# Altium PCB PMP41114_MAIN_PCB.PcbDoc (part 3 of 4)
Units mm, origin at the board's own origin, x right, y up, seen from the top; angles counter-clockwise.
Board outline 159.1 x 70 mm, 6 copper layers (Top Layer, Signal Layer 1, Signal Layer 2, Signal Layer 3, Signal Layer 4, Bottom Layer), stack 1.671 mm thick; 188 components, 146 nets, 720 pads, 326 vias.
Unrouted connection lines stored in the file: 209.
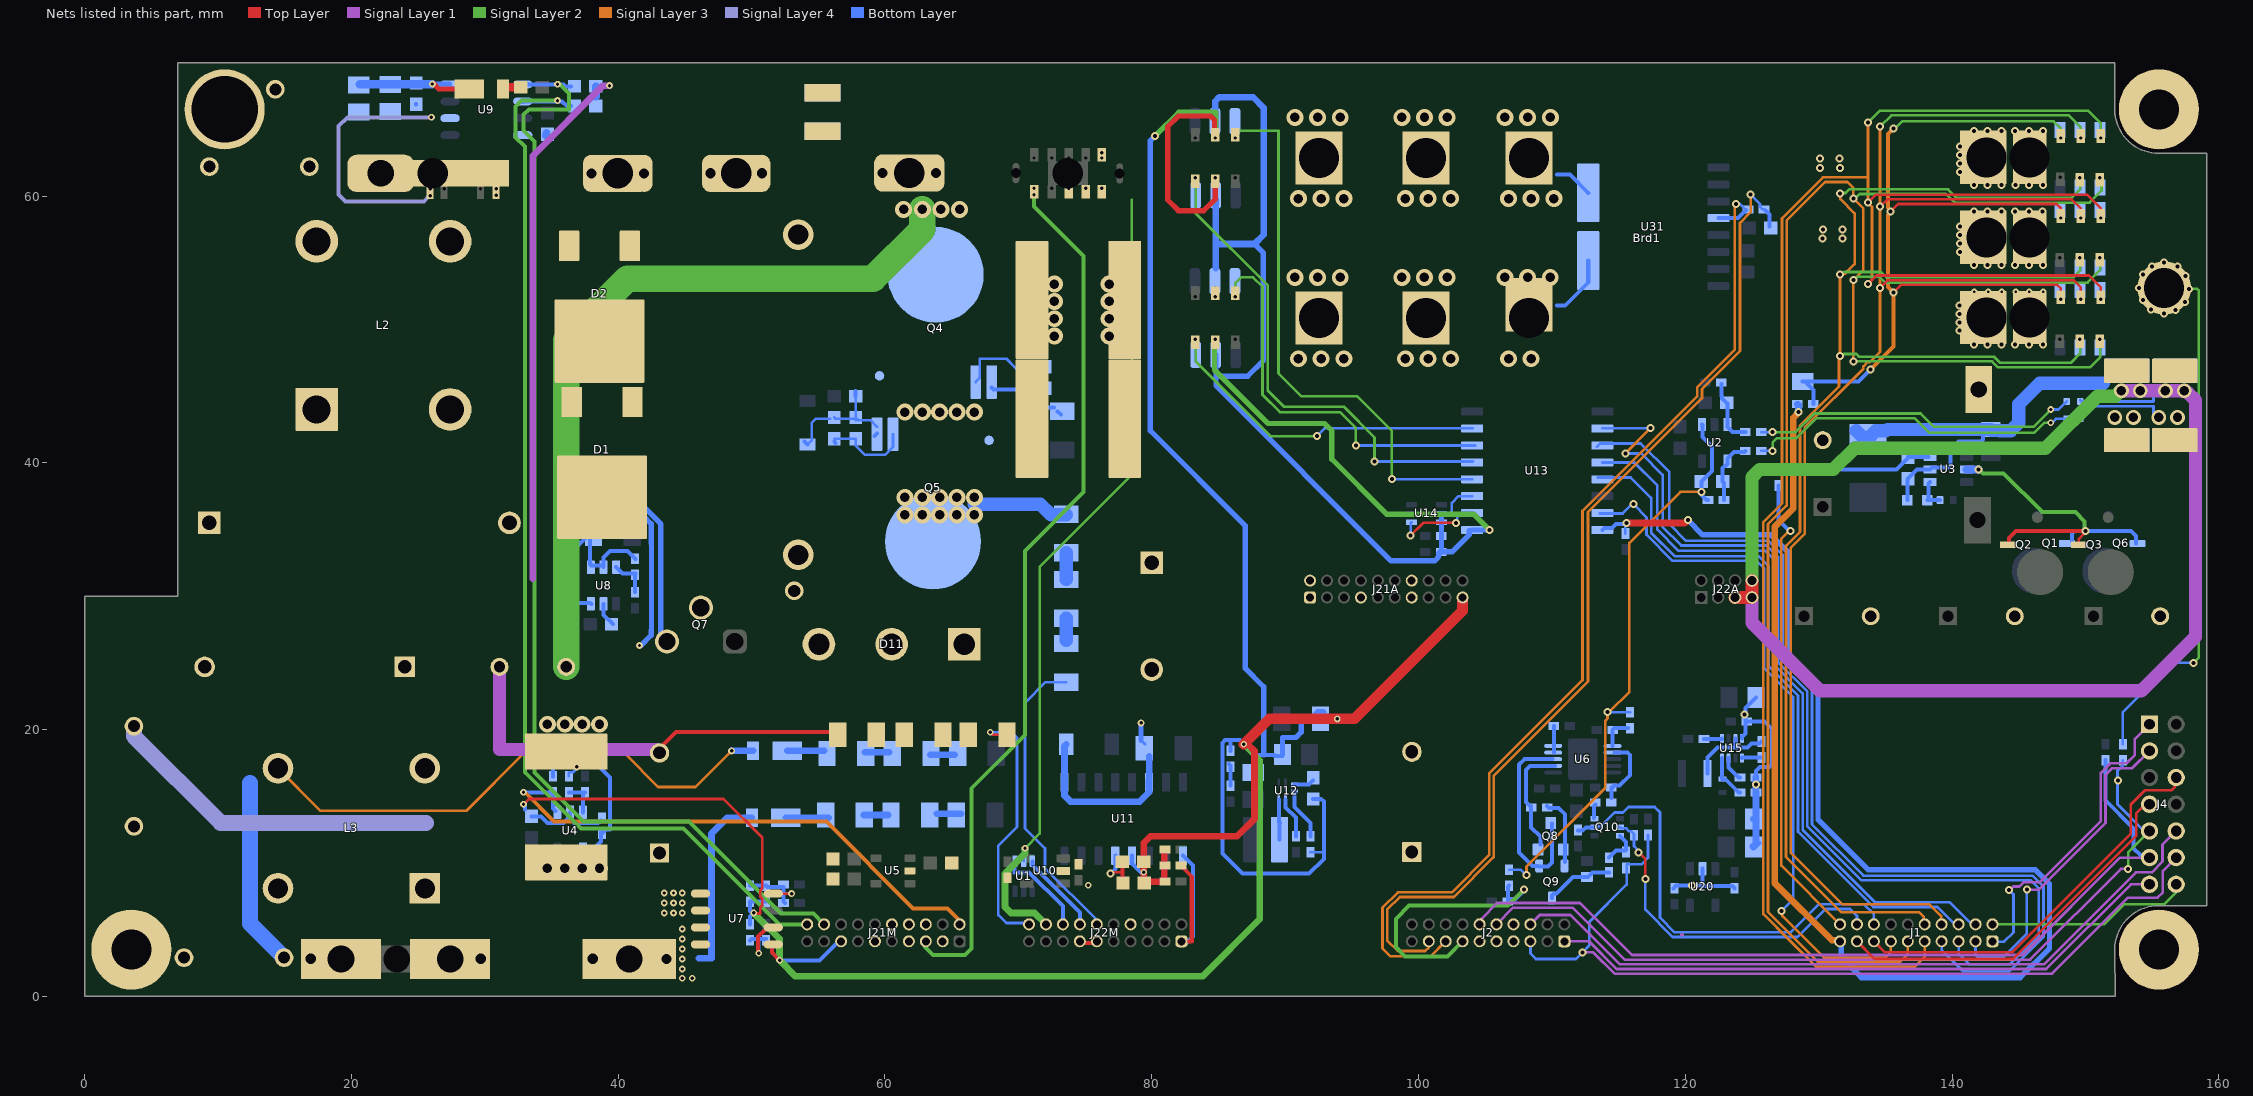
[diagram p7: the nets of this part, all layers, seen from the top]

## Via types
v1: diameter 0.6, hole 0.3, Top Layer to Bottom Layer, tented both sides, 153 vias
v2: diameter 0.508, hole 0.254, Top Layer to Bottom Layer, tented both sides, 73 vias
v3: diameter 1.27, hole 0.711, Top Layer to Bottom Layer, tented both sides, 70 vias
v4: diameter 0.5, hole 0.2, Top Layer to Bottom Layer, tented both sides, 12 vias
v5: diameter 1.1, hole 0.711, Top Layer to Bottom Layer, tented both sides, 8 vias
v6: diameter 0.5, hole 0.2, Top Layer to Bottom Layer, 6 vias
v7: diameter 1.4, hole 0.9, Top Layer to Bottom Layer, tented both sides, 2 vias
v8: diameter 4, hole 3, Top Layer to Bottom Layer, tented both sides, 1 vias
v9: diameter 4/3/4/4/4/4 (per signal layer), hole 3, Top Layer to Bottom Layer, tented both sides, 1 vias

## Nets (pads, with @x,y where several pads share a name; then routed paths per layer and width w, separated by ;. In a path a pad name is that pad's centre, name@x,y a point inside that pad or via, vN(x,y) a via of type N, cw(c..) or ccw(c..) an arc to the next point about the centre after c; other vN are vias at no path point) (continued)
IMON: C19.1 J2.5 J4.12 R13.2 | length 67
  Signal Layer 1 w0.2: J2.5@108.39,4.13 J2.5@108.468,4.052 ; v1(112.3,3.3) 113.1,3.3 114.7,1.7 147.5,1.7 153.2,7.4 155.4,7.4 155.8,7.8 155.8,9.4 J4.12@156.8,10.4
  Signal Layer 2 w0.2: J4.12@156.3,10.4 J4.12@156.8,10.4
  Bottom Layer w0.2: J2.5@108.39,4.13 108.39,3.21 108.8,2.8 111.8,2.8 v1(112.3,3.3) 112.8,3.8 112.8,5.59 115.6,8.39 115.6,9.9 116.7,9.9 117.2,10.4 C19.1@117.2,12.1
iMon_EN: C27.1 J1.16 Q10.2 | length 33.4
  Bottom Layer w0.2: Q10.2@113.2,12.675 113.301,12.776 113.688,12.776 114.696,13.785 115.335,13.785 115.75,14.2 117.7,14.2 118.1,13.8 118.1,5.9 119.2,4.8 127.9,4.8 130,6.9 133.4,6.9 134.14,6.16 J1.16@134.14,5.4
  Bottom Layer w0.3: C27.1@111.96,12.42 112.295,12.42 112.55,12.675 Q10.2@113.2,12.675
iMon_Gain: C28.1 J1.18 Q10.5 | length 25.9
  Top Layer w0.2: v1(116.5,10.8) v1(116.5,10.8) 117,10.298 v1(117,8.8)
  Bottom Layer w0.2: Q10.5@115.1,12.675 115.17,12.605 115.564,12.605 115.794,12.375 115.95,12.375 116.15,12.175 116.15,11.625 ; 116.15,11.475 116.15,11.625 ; v1(116.5,10.8) 116.5,10.908 116.15,11.258 116.15,11.625 ; v1(117,8.8) 117,6.505 119.055,4.45 128.4,4.45 130.5,6.55 132.35,6.55 132.867,6.033 132.867,5.403 J1.18@132.87,5.4
Iout-local: C9.1 J2.13 R7.2 | length 21.2
  Signal Layer 2 w0.3: J2.13@103.31,4.13 102.18,3 99,3 98.3,3.7 98.3,5.8 99.3,6.8 106.7,6.8 v1(107.9,8)
  Bottom Layer w0.3: C9.1@106.7,7.1 106.7,8.2 R7.2@106.8,8.3 ; C9.1@106.8,7.1 106.95,7.25 107.249,7.25 107.843,7.844 107.843,7.943 v1(107.9,8)
Ip_sns: J2.15 R10.2 U31.6 | length 77.7
  Signal Layer 3 w0.2: J2.15@102.04,4.13 100.91,3 97.9,3 97.3,3.6 97.3,6.65 98.45,7.8 102.5,7.8 105.3,10.6 105.3,16.7 112.3,23.7 112.3,36.395 120.9,44.995 120.9,45.673 123.7,48.473 123.7,59.1 v1@123.8,59.2
  Bottom Layer w0.2: v1(123.8,59.4) 124.1,59.4 124.55,58.95 R10.2@124.6,58.9
  Bottom Layer w0.3: U31.6@122.475,58.335 123.935,58.335 R10.2@124.55,58.95
Isns_n: R6.1 RJ02.1 | length 25.2
  Signal Layer 2 w0.2: v1(126.55,40.9) 126.55,41.522 126.879,41.851 128.325,41.851 129.824,43.35 137.2,43.35 138.3,42.25 146.157,42.25 146.907,43 v2(147.4,43)
  Bottom Layer w0.2: R6.1@125.7,40.9 v1(126.55,40.9) ; v2(147.4,43) 147.483,43 147.783,43.3 RJ02.1@148.588,43.3
Isns_p: R8.1 RJ01.1 | length 24.7
  Signal Layer 2 w0.2: v1(126.55,42.3) 128.279,42.3 129.679,43.7 137.65,43.7 138.65,42.7 146.112,42.7 v2(147.406,43.994)
  Bottom Layer w0.2: R8.1@125.7,42.3 v1(126.55,42.3) ; v2(147.406,43.994) 147.981,43.994 148.438,44.45 148.45,44.45 148.588,44.588 RJ01.1@148.588,44.6
LFFET_HS: C64.1 J21M.20 U9.2 | length 83.2
  Signal Layer 2 w0.3: v2(35.45,67.15) 32.75,67.15 32.3,66.7 32.3,64.4 33,63.7 33,16.8 37.2,12.6 44.9,12.6 52.1,5.4 J21M.20@54.17,5.4
  Bottom Layer w0.3: U9.2@32.85,67.05 32.9,67.1 35.8,67.1 36.15,66.75 C64.1@36.475,66.75
LFFET_LS: C65.1 J21M.18 U9.1 | length 85.5
  Signal Layer 2 w0.3: v2@35.45,68.35 35.55,68.45 36.3,67.7 36.3,66.5 33.304,66.5 32.9,66.096 32.9,64.9 33.727,64.073 33.727,20.817 33.727,19.983 33.727,16.773 37.4,13.1 45.3,13.1 52.2,6.2 54.64,6.2 J21M.18@55.44,5.4
  Bottom Layer w0.3: U9.1@33.175,68.425 33.175,68.4 33.2,68.375 v2(35.45,68.375) 35.9,68.375 36.05,68.225 C65.1@36.475,68.225
Line: C45.2 D1.1 D1.3 D2.4 L2.3 L4.1 pad.4 | length 0.3
  Signal Layer 3 w0.3: L4.1@53.5,33.1 L4.1@53.7,33.3
  other v7: 53.2,30.4
LLC-FLT: U13.10 U14.4 | length 6.5
  Top Layer w0.2: v1(99.411,34.555) 100.356,35.5 v1@102.7,35.5
  Bottom Layer w0.2: v1(99.411,34.555) 99.411,35.486 U14.4@99.475,35.55 ; v1(102.8,35.5) 102.9,35.6 102.9,36.1 103.025,36.225 U13.10@104.025,36.225
LLC-FLT-s: J1.13 U13.7 | length 53.2
  Signal Layer 3 w0.2: v1(127.2,6.4) 127.274,6.326 127.274,6.026 130.4,2.9 135,2.9 135.41,3.31 J1.13@135.41,4.13
  Bottom Layer w0.2: U13.7@113.585,36.2 115.3,36.2 116,36.9 v1(116.1,36.9) 117.096,35.904 117.096,34.609 119.055,32.65 125.355,32.65 125.9,32.105 125.9,24.61 128.1,22.41 128.1,7.3 v1(127.2,6.4)
Lout: L3.2 pad.1@29.698,2.821 pad.3
LS-BUS: J2.6 J4.10 | length 55.1
  Signal Layer 1 w0.2: J2.6@108.39,5.4 109.09,6.1 111.4,6.1 115.1,2.4 146.88,2.4 153.78,9.3 154.973,9.3 155.781,10.108 155.781,11.381 J4.10@156.8,12.4
MID-1: Brd1.P9a U31.1 | length 4.7
  Bottom Layer w0.3: Brd1.P9a@110.4,51.8 111,51.8 112.725,53.525 U31.1@112.725,55.16
  other v3: 106.747,47.8 108.447,47.8 106.478,53.899 108.178,53.899 109.878,53.899
MID-2: Brd1.P9b U31.2 | length 2.9
  Bottom Layer w0.3: Brd1.P9b@110.4,61.6 111.365,61.6 U31.2@112.725,60.24
  other v3: 106.748,59.8 108.448,59.8 110.148,59.8 106.478,65.899 108.178,65.899 109.878,65.899
N: D12.2 pad.1@38.098,2.821 pad.1@43.623,2.796 pad.2 U7.3 U7.4 | length 13.8
  Bottom Layer w0.5: 46.041,2.85 47,2.85 47,12.2 48.2,13.4 D12.2@50.025,13.4
  other v2: 44.8,1.35 45.55,1.35 44.8,2.05 44.8,2.8 44.8,3.55 44.8,4.3 44.8,5.05
NetBrd1_S6: Brd1.S6 C11.2 pad.1@148.15,52.25 pad.1@148.15,58.35 pad.1@148.15,64.35 R24.2 | length 67.7
  Top Layer w0.2: v1(135.4,58.85) 135.95,59.4 147.833,59.4 148.15,59.083 pad.1@148.15,58.35 ; v1(135.6,52.769) 136.17,53.339 147.861,53.339 148.15,53.05 pad.1@148.15,52.25
  Signal Layer 2 w0.2: v1(135.6,65.05) 135.708,65.05 136.258,65.6 147.613,65.6 148.15,65.063 148.15,64.75 pad.1@148.15,64.35
  Signal Layer 2 w0.3: v1@135.31,58.793 v1@135.317,58.8
  Signal Layer 3 w0.2: pad.1@148.1,52.3 pad.1@148.15,52.25
  Signal Layer 3 w0.3: v1(133.9,47) 135.6,48.7 v1(135.6,52.769) 135.2,53.169 135.2,58.569 135.4,58.769 v1(135.4,58.85) ; 135.2,59.131 135.2,64.65 v1(135.6,65.05)
  Bottom Layer w0.3: C11.2@128.8,46.1 C11.2@128.965,46.1 ; R24.2@129.6,44.4 129.6,45.465 C11.2@128.965,46.1 ; v1(133.9,47) 133,46.1 C11.2@128.965,46.1
NetBrd1_S8: Brd1.S8 pad.1@142,45.5
  other v1: 141.64,48.86 142.672,48.86 143.704,48.86 140.57,49.9 140.57,50.533 140.57,51.167 140.57,51.8 141.64,54.84 142.672,54.84 143.704,54.84 140.6,55.8 140.6,56.433 130.3,56.8 131.8,56.8 140.6,57.067 130.333,57.5 131.8,57.5 140.6,57.7 141.63,58.83 142.662,58.83 143.694,58.83 141.636,60.83 142.668,60.83 143.7,60.83 140.6,61.8 130.1,62.1 131.6,62.1 140.6,62.433 130.1,62.8 131.567,62.8 140.6,63.067 140.6,63.7 141.64,64.88 142.672,64.88 143.704,64.88
  other v4: 141.668,52.82 142.7,52.82 143.732,52.82
NetC7_1: C7.1 R1.2 R6.2 U2.4 | length 4.9
  Bottom Layer w0.3: R1.2@122.9,37.2 122.9,38.5 C7.1@122.8,38.6 122.8,39.599 122.976,39.775 123,39.775 123.15,39.925 123.15,40.325 123.65,40.825 124.425,40.825 R6.2@124.5,40.9
NetC13_1: C13.1 R8.2 R9.2 U2.3 | length 4.9
  Bottom Layer w0.3: R9.2@122.7,45.9 122.7,45.001 122.75,44.951 122.75,44.825 123.075,44.5 C13.1@123.1,44.5 123.15,44.45 U2.3@123.15,42.875 123.15,42.675 123.525,42.3 R8.2@124.5,42.3
NetC14_2: C14.2 R11.1 U3.1 | length 2.4
  Bottom Layer w0.3: U3.1@138.35,38.55 138.25,38.45 138.25,37.3 C14.2@138.15,37.2 R11.1@139.1,37.2
NetC21_1: C21.1 R17.2 U3.3 | length 11.7
  Bottom Layer w0.3: R17.2@126.9,39.6 R17.2@126.95,39.65 ; R17.2@127,39.5 135.825,39.5 136.7,40.375 C21.1@136.7,40.4 136.7,40.45 U3.3@138.225,40.45
NetC23_1: C23.1 R15.2 U6.6 | length 2.4
  Bottom Layer w0.3: U6.6@114.55,18.775 C23.1@114.55,19.975 114.675,20.1 R15.2@115.7,20.1
NetC24_1: C24.1 U6.4 U6.5 | length 2
  Bottom Layer w0.3: U6.4@110.15,18.275 C24.1@110.15,20.275
NetC25_2: C25.2 D4.2 Q9.3 | length 5.2
  Bottom Layer w0.3: Q9.3@110,7.375 110,7.575 110.15,7.725 110.35,7.725 111.585,8.96 112.695,8.96 113.036,9.301 D4.2@114.265,9.301
NetC29_1: C29.1 U15.5 | length 1.5
  Bottom Layer w0.3: U15.5@124.25,17.86 124.25,17.9 C29.1@125.7,17.9
NetC29_2: C29.2 L6.1 U15.3 | length 6.4
  Bottom Layer w0.3: L6.1@121.65,16.7 121.65,17.9 122.4,18.65 123.75,18.65 ; U15.3@123.75,19.34 123.75,18.65 ; C29.2@125.7,19.1 125.55,18.95 124.95,18.95 124.65,18.65 123.75,18.65
NetC39_1: C39.1 D8.2 Q5.1 R57.2 R58.1 | length 9.6
  Bottom Layer w0.2: D8.2@54.2,41.362 54.5,41.662 54.5,43 54.8,43.3 C39.1@55.9,43.3 ; C39.1@56.2,43.4 56.3,43.3 R57.2@57.8,43.3 ; R57.2@57.8,43.2 R57.2@57.8,43.3 ; R58.1@57.8,45 R57.2@57.8,43.4 ; Q5.1@59.4,42.7 58.9,43.2 58,43.2 R57.2@57.8,43.4 ; R57.2@57.8,43.3 R57.2@57.8,43.4
  Bottom Layer w0.3: D8.2@53.963,41.6 D8.2@54.2,41.362 ; R58.1@57.8,45 R58.1@57.8,45.4 ; Q5.1@59.2,42 Q5.1@59.4,42.2
NetC40_2: C40.2 D10.2 Q4.1 R64.2 R65.1 | length 7.8
  Bottom Layer w0.3: Q4.1@68,45.65 68.15,45.5 R65.1@70.4,45.5 ; D10.2@70.5,44.1 D10.2@70.5,44.3 ; D10.2@70.5,44.137 D10.2@70.5,44.3 ; D10.2@70.7,44.137 R64.2@72.663,44.137 ; C40.2@71.7,45.5 R65.1@70.4,45.5 ; R64.2@72.953,43.847 R64.2@73.19,43.61 ; R65.1@70.4,45.5 70.5,45.4 D10.2@70.5,44.337 ; D10.2@70.5,44.3 D10.2@70.5,44.337 ; D10.2@70.5,44.3 D10.2@70.5,44.337
  Bottom Layer w0.4: D10.2@70.663,44.3 D10.2@70.7,44.337
NetC41_2: C41.2 C44.2 D9.2 L2.1 L3.3 | length 55.5
  Top Layer w1: L2.1@17.4,43.5 L2.1@17.7,43.2
  Signal Layer 3 w0.2: L3.3@14.5,17.1 17.69,13.91 28.61,13.91 32.9,18.2 40.5,18.2 43,15.7 45.8,15.7 v2(48.5,18.4)
  Bottom Layer w0.5: v2(48.5,18.4) D9.2@50.125,18.4
  Bottom Layer w1.2: 12.4,16 12.4,5.45 C41.2@14.95,2.9
NetC44_1: C44.1 C48.1 L2.2 L3.4 | length 25.3
  Signal Layer 4 w1.2: C48.1@3.7,20.25 3.7,19.5 10.2,13 25.6,13
NetC54_1: C54.1 C55.1 R82.1 R83.1 U7.8 | length 5.8
  Top Layer w0.2: U7.8@51.625,7.705 51.63,7.7 v2(53,7.7)
  Bottom Layer w0.2: 52.4,7.7 v2(53,7.7)
  Bottom Layer w0.3: C54.1@49.9,8.3 C55.1@51.1,8.3 51.2,8.2 52.4,8.2 52.4,7.7 52.4,7.1 R82.1@52.5,7
NetC56_1: C56.1 R86.1 U7.6 | length 4.7
  Top Layer w0.3: v2@50.5,3.364 50.5,4.5 51.065,5.065 U7.6@51.525,5.065
  Bottom Layer w0.3: C56.1@49.9,4.2 50,4.3 50.6,4.3 ; v2(50.538,3.224) 50.538,4.238 50.6,4.3 ; R86.1@51.1,4.3 50.6,4.3
NetC57_1: C57.1 C59.1 C61.2 D15.1 U9.8 | length 11.8
  Top Layer w0.4: v2@26.15,68.425 26.55,68.025 D15.1@28.825,68.025
  Bottom Layer w0.4: C59.1@20.675,68.375 22.916,68.375 C57.1@22.925,68.366 ; v2@26.075,68.38 U9.8@27.325,68.38
  Bottom Layer w0.635: C59.1@20.63,68.38 v2@26.075,68.38
  other v2: 26.075,68.4
NetC58_1: C58.1 R88.2 U8.6 | length 3
  Bottom Layer w0.3: U8.6@39.85,32.175 40.325,31.7 C58.1@41.2,31.7 ; R88.2@41.25,30.3 C58.1@41.25,31.6 41.25,31.65 C58.1@41.3,31.7
NetC75_1: C75.1 R98.2 U11.5 | length 4.2
  Top Layer w0.2: v1(76.9,9.2) 77,9.3 77.8,9.3
  Top Layer w0.3: C75.1@77.8,10.1 77.8,8.5 R98.2@77.9,8.4
  Bottom Layer w0.3: v1(76.9,9.2) 77.265,9.565 U11.5@77.265,10.55
NetC215_1: C215.1 U12.8 | length 3.9
  Bottom Layer w0.3: U12.8@90.7,15.4 90.7,14.2 91.9,13 C215.1@91.9,12
NetD4_1: D4.1 Q10.6 R13.1 | length 2.8
  Bottom Layer w0.3: D4.1@114.265,10.401 114.789,10.925 115.5,10.925 115.55,10.975 115.55,11.575 Q10.6@115.1,12.025
NetD9_1: D9.1 R60.2 | length 2.8
  Bottom Layer w0.5: D9.1@52.675,18.4 R60.2@55.45,18.4
NetD11_1: D11.1 D11.3 L1.1 Q7.2
NetD12_1: D12.1 R84.2 | length 3.2
  Bottom Layer w0.5: D12.1@52.575,13.4 R84.2@55.777,13.4
NetD15_2: D15.2 R89.1 | length 1
  Top Layer w0.635: D15.2@31.575,68.15 R89.1@32.6,68.15
NetJ22M_14: J22M.14 U1.3 | length 6.2
  Bottom Layer w0.3: U1.3@71.05,10.125 71.05,9.85 74.61,6.29 J22M.14@74.61,5.4
NetJ22M_16: J22M.16 U1.1 | length 6.7
  Bottom Layer w0.3: U1.1@69.7,9.9 69.7,9.3 70.8,9.3 73.34,6.76 J22M.16@73.34,5.4
NetL5_1: L5.1 U12.2 | length 3.1
  Bottom Layer w0.3: U12.2@89.525,14.775 89.525,13.075 L5.1@89.6,13 ; L5.1@89.575,11.75 L5.1@89.575,13
NetQ8_1: Q8.1 Q9.2 R12.2 | length 5.2
  Bottom Layer w0.3: R12.2@109.65,14.275 109.8,14.125 110.5,14.125 111,13.625 111,10.975 Q9.2@111,10.082
NetQ8_2: Q8.2 R12.1 U6.2 | length 8.4
  Bottom Layer w0.3: Q8.2@109.15,11.375 109.15,11.975 108.45,12.675 108.45,14.275 108.35,14.275 108.05,14.575 108.05,16.975 108.35,17.275 U6.2@110.225,17.275
NetQ8_3: Q8.3 Q9.1 U6.3 | length 15.2
  Bottom Layer w0.3: Q8.3@110,12.975 110,10.025 109.716,9.741 108.984,9.741 108.95,9.775 108.55,9.775 107.55,10.775 107.55,17.375 107.95,17.775 U6.3@110.05,17.775
NetQ10_3: Q10.3 R14.1 | length 1
  Bottom Layer w0.3: Q10.3@113.15,13.375 113.15,14.28 R14.1@113.25,14.38
NetR14_2: R14.2 R16.2 U6.7 | length 5.2
  Bottom Layer w0.3: 114.45,14.875 R16.2@114.45,15.675 ; R16.2@114.55,15.675 114.668,15.793 115.068,15.793 115.85,16.575 115.85,18.075 115.65,18.275 U6.7@114.675,18.275
NetR20_1: R20.1 U15.1 | length 1.4
  Bottom Layer w0.3: R20.1@121.4,19.3 122.75,19.3 U15.1@122.75,19.34
NetR21_2: R21.2 U15.7 | length 1.9
  Bottom Layer w0.3: U15.7@123.25,17.86 123.25,17.15 124,16.4 R21.2@124.1,16.4
NetR22_2: R22.2 R23.1 U15.8 | length 3.3
  Bottom Layer w0.3: R22.2@122.75,16.308 U15.8@122.75,17.86 ; R22.2@122.8,16.308 122.841,16.267 123.032,16.267 124,15.3 R23.1@124.1,15.3
NetR42_1: R42.1 R46.2 U4.4 | length 13
  Bottom Layer w0.3: R42.1@35.1,16.5 35.1,17.3 35.8,18 37.8,18 39.4,16.4 39.4,12.5 39.1,12.5 R46.2@38.8,12.2 ; U4.4@37.35,11.05 38.15,11.05 38.7,11.6 R46.2@38.7,12.3
NetR43_2: R43.2 R45.2 U4.3 | length 2.7
  Bottom Layer w0.3: R43.2@36.3,15.3 R45.2@37.35,15.3 ; U4.3@37.35,13.8 R45.2@37.35,15.3 ; R45.2@37.5,15.3 R45.2@37.35,15.3
NetR47_1: R47.1 R48.2 | length 0.1
  Top Layer w0.3: R47.1@59.35,19.6 R47.1@59.45,19.7
NetR48_1: R48.1 R49.2 | length 0
  Top Layer w0.3: R49.2@66.677,19.623 R49.2@66.7,19.6
NetR50_1: R50.1 R51.2 | length 2.1
  Bottom Layer w0.2: R51.2@73.6,31.1 R51.2@73.6,31.25
  Bottom Layer w1: R51.2@73.6,31.25 R50.1@73.6,33.25
NetR51_1: R51.1 R52.2 | length 1.6
  Bottom Layer w1: R52.2@73.6,26.7 R51.1@73.6,28.35
NetR60_1: R60.1 R61.2 | length 1.8
  Bottom Layer w0.5: R60.1@58.5,18.3 R61.2@60.325,18.3
NetR61_1: R61.1 R62.2 | length 1.8
  Bottom Layer w0.5: R61.1@63.4,18.1 R62.2@65.225,18.1
NetR84_1: R84.1 R85.2 | length 1.8
  Bottom Layer w0.5: R84.1@58.4,13.6 R85.2@60.225,13.6
NetR85_1: R85.1 R87.2 | length 1.8
  Bottom Layer w0.5: R85.1@63.9,13.7 R87.2@65.725,13.7
NetR90_2: R90.2 U8.2 | length 1.8
  Bottom Layer w0.3: U8.2@38.9,29.425 38.9,28.6 R90.2@39.6,27.9
NetR91_1: R91.1 U8.3 | length 1.6
  Bottom Layer w0.3: R91.1@36.4,29.5 37.9,29.5 U8.3@38,29.4
NetR248_2: R248.2 R251.1 | length 1.6
  Bottom Layer w0.3: R248.2@85.8,17.4 85.9,17.3 R248.2@85.9,17.2 R251.1@85.9,15.8
NetR249_2: R249.2 U12.7 | length 1.5
  Bottom Layer w0.3: U12.7@90.7,15.9 91.8,15.9 R249.2@92.1,16.2
NetR271_1: R271.1 U12.1 | length 3.1
  Bottom Layer w0.3: U12.1@90.025,14.775 90.025,14.175 90.8,13.4 R271.1@90.8,12
Neutral: C42.2 C45.1 C57.2 C59.2 C61.1 L2.4 pad.1@22.196,61.696 pad.1@25.9,60.55 pad.1@26.109,61.696 U9.6 | length 20.1
  Signal Layer 3 w0.3: pad.1@21.6,60.6 pad.1@21.9,60.6
  Signal Layer 4 w0.3: pad.1@25.9,60.075 25.425,59.6 19.575,59.6 19.05,60.125 19.05,65.25 19.7,65.9 v2(26,65.9)
  Bottom Layer w0.3: C61.1@24.85,66.875 C61.1@24.85,66.9 ; v2@25.94,65.84 v2(26,65.9) v2@26.06,65.84
  other v2: 25.9,60.025
Nout: L3.1 U7.1 U7.2
  other v2: 43.45,6.25 44.15,6.25 44.8,6.25 43.45,7 44.15,7 44.8,7 43.45,7.75 44.15,7.75 44.8,7.75
ORING-EN: J1.20 R17.1 | length 35.5
  Signal Layer 3 w0.2: v1(127.9,34.9) 127.792,34.9 127.2,34.308 127.2,9.8 J1.20@131.6,5.4
  Bottom Layer w0.3: R17.1@127,38.3 127,35.7 127.318,35.382 127.337,35.382 127.819,34.9 v1(127.9,34.9)
ORING_GATE: Q1.9 Q2.9 Q3.9 Q6.9 U3.5 | length 24.8
  Top Layer w0.2: Q3.9@149.5,33.9 149.5,34.3 v1@149.85,34.65
  Top Layer w0.3: Q2.9@144.2,33.85 144.272,33.922 144.272,34.375 144.797,34.9 v1(150,34.9)
  Signal Layer 2 w0.3: v1(142,39.5) 142.026,39.5 142.326,39.2 143.873,39.2 146.773,36.3 149.249,36.3 149.943,35.606 149.943,34.957 v1(150,34.9)
  Bottom Layer w0.3: Q1.9@149,34.1 149,34.7 149.2,34.9 v1(150,34.9) 153.4,34.9 153.8,34.5 Q6.9@153.8,33.95
  Bottom Layer w0.6: U3.5@141.1,39.5 v1(142,39.5)
PE: C41.1 C42.1 C48.2 pad.1@3.5,3.5 pad.1@10.5,66.5 pad.1@155.5,3.5 pad.1@155.5,66.5 | length 0.1
  Signal Layer 1 w0.254: C41.1@7.45,3.2 C41.1@7.55,3.1
  other v7: 14.3,68
PGND: Brd1.P3a Brd1.P3b Brd1.P4a Brd1.P4b Brd1.P7a Brd1.P7b C2.1 C3.2 C15.2 C22.2 C26.2 C31.1 C32.1 C33.1 C54.2 C55.2 C56.2 C58.2 C60.2 C62.2 C63.2 C68.2 C69.2 C70.2 C71.2 C73.2 C75.2 C76.2 C114.1 C120.1 C123.1 C130.1 C215.2 J21A.7 J21A.13 J21A.14 J21A.19 J21M.6 J21M.7 J21M.8 J21M.10 J21M.15 J22M.8 J22M.11 J22M.13 J22M.18 pad.1@73.775,60.575 pad.1@75.05,60.575 pad.1@76.25,60.575 pad.1@76.25,62.85 pad.1@84.75,52.45 pad.1@84.75,64.35 pad.1@84.775,49.275 pad.1@84.775,61.375 Q7.3 R46.1 R77.1 R98.1 R150.1 R248.1 R249.1 U1.2 U4.2 U5.2 U7.5 U8.4 U8.5 U10.2 U11.4 U13.9 U13.11 U14.2 U14.3 | length 454
  Top Layer w0.2: v2(32.9,14.4) 33.3,14.8 47.9,14.8 50.8,11.9 50.8,8.083 50.65,7.933 50.65,7.477 50.8,7.327 50.8,6.813 50.65,6.663 50.65,6.21 50.207,6.21 v2(50.158,6.258)
  Top Layer w0.3: U7.5@51.525,3.795 51.525,3.275 v2(52.1,2.7) ; J22M.13@74.41,4 J22M.11@75.7,4 ; J21A.14@99.49,31.17 J21A.14@99.5,31.16
  Top Layer w0.4: pad.1@84.7,65 84.7,65.7 84.4,66 82,66 81.2,65.2 81.2,59.7 82,58.9 83.9,58.9 84.75,59.75 84.75,60.555
  Top Layer w0.5: R98.1@79.4,8.7 v2(79.4,9.3) C75.2@79.4,10.1 79.4,11.5 79.9,12 86.4,12 87.7,13.3 87.7,18.4 87.2,18.9 v2(86.9,18.9) ; R98.1@79.55,8.6 C76.2@80.9,8.6 ; C76.2@80.95,8.75 C68.2@80.95,9.775 ; C68.2@80.95,9.85 C69.2@80.95,10.975
  Top Layer w0.8: v2(86.9,18.9) 88.8,20.8 v2(93.9,20.8) 95.2,20.8 103.3,28.9 J21A.19@103.3,29.9
  Signal Layer 2 w0.2: v2(70.5,11.1) 71.6,12.2 71.6,32.2 78.5,39.1 78.5,59.725 ; pad.1@84.775,53.125 84.8,53.1 pad.1@84.8,53
  Signal Layer 2 w0.3: J21A.14@99.49,31.17 99.49,31.29 J21A.14@99.5,31.3 ; J21A.19@103.2,30 J21A.19@103.3,30.1
  Signal Layer 2 w0.4: v1(80.25,64.5) 82.025,66.275 84.8,66.275 pad.1@84.8,64.82 ; pad.1@84.7,48.754 84.7,46.964 88.714,42.95 92.95,42.95 93.5,42.4 93.5,40.264 97.614,36.15 104.123,36.15 v1(105.312,34.962)
  Signal Layer 2 w0.5: v2(50.158,6.258) 52.1,4.317 v2(52.1,2.7) ; v2@52.2,2.6 53.3,1.5 83.8,1.5 88.1,5.8 88.1,17.7 v2(86.9,18.9) ; v2(70.5,11.1) v2(70.5,11.1) 70.498,10.698 69,9.2 69,6.7 69.45,6.25 71.22,6.25 J22M.18@72.07,5.4
  Signal Layer 4 w0.2: pad.1@84.75,53.15 pad.1@84.8,53.1 ; pad.1@84.75,60.75 pad.1@84.8,60.8
  Bottom Layer w0.2: C60.2@38.15,34.7 C60.2@38.15,35.45 ; U1.2@70.4,10.125 70.4,11 v2(70.5,11.1) ; C215.2@91.9,10.8 92.9,10.8 ; C70.2@92.5,21 C70.2@92.591,21.091 ; C15.2@101.7,34.5 C15.2@101.725,34.5 ; U14.2@101.725,36.2 102.5,36.2 102.5,37 102.995,37.495 U13.11@104.025,37.495
  Bottom Layer w0.3: v2(32.9,14.4) 33,14.3 33,14 ; C26.2@33.5,13.5 34.2,13.5 34.7,13 35.9,13 U4.2@36.4,13.5 ; U4.2@36.4,13.8 36.4,13.3 36.7,13 38.5,13 R46.1@38.7,13.2 ; R77.1@36.4,32.8 36.4,33.2 C60.2@37.9,34.7 ; U8.4@37.9,32.4 37.9,34.45 C60.2@38.15,34.7 ; U8.4@37.95,32.3 U8.5@38.8,32.3 ; U8.5@38.9,32.175 38.9,32.9 39.4,33.4 40.7,33.4 C58.2@41.3,32.8 ; C56.2@49.9,5.4 49.9,6 v2(50.158,6.258) ; C54.2@49.9,7 49.9,6.4 v2@50,6.3 ; C54.2@49.9,7.1 C55.2@51.1,7.1 ; v2(52.1,2.7) 55.1,2.7 56.3,3.9 ; U11.4@78.535,10.55 78.535,9.965 79.2,9.3 v2(79.4,9.3) ; R248.1@85.9,18.4 85.9,19.2 ; v2(86.9,18.9) 86.6,19.2 85.9,19.2 ; C73.2@87.6,16.791 87.6,18.1 88.4,18.1 C71.2@89.2,18.1 ; C71.2@89.2,18 C71.2@89.8,18 ; R249.1@92.1,14.8 92.7,14.8 92.9,14.6 92.9,13.2 92.9,10.9 ; 92.9,10.8 92.9,10.3 91.8,9.2 86.8,9.2 85.3,10.7 85.3,19 85.5,19.2 85.9,19.2
  Bottom Layer w0.4: C60.2@38.15,35.45 39.3,36.6 42,36.6 43.2,35.4 43.2,27.06 Q7.3@43.66,26.6 ; C60.2@38.75,35.3 39.1,35.3 39.8,36 41.9,36 42.477,35.423 42.477,33.98 42.5,33.957 42.5,27.493 42.477,27.47 42.477,27.077 41.7,26.3 v2(41.6,26.3) ; v1(80.25,64.5) 79.9,64.15 79.9,42.4 87,35.3 87,24.6 88.4,23.2 88.4,18.1 ; Brd1.P3a@84.812,48.101 84.812,46.5 ; 87.7,56.4 88.37,55.73 88.37,47.67 87.2,46.5 84.812,46.5 ; C71.2@89.809,18.125 89.809,19.4 90.8,19.4 91.2,19.8 91.2,20.7 91.3,20.8 C70.2@92.65,20.8 v2@93.7,20.8 ; C22.2@101.7,33.3 101.6,33.3 101.5,33.2 101.5,32.934 101.216,32.65 97.95,32.65 84.812,45.788 84.812,46.5 ; U14.2@101.725,36.2 U14.3@101.725,35.55 101.725,34.5 101.725,33.325 102.525,33.325 103.8,34.6 U13.9@103.8,34.9 ; U13.9@104.025,34.955 104.028,34.958 105.308,34.958 v1(105.312,34.962)
  Bottom Layer w0.5: Brd1.P4b@84.76,65.601 84.76,67.107 85.053,67.4 87.607,67.4 88.4,66.607 88.4,57.1 87.7,56.4 84.8,56.4 ; Brd1.P4a@84.8,54.6 84.8,56.4 ; Brd1.P3b@84.8,59.7 84.8,56.4 ; C70.2@92.288,21.112 92.452,21.277 C70.2@92.848,21.277
  other v2: 75.238,8.324 76.257,63.239
  other v3: 34.7,9.6 36,9.6 37.3,9.6 38.6,9.6 91,47.8 92.7,47.8 94.4,47.8 76.8,49.5 76.8,50.8 76.8,52.1 76.8,53.4 90.731,53.899 92.431,53.899 94.131,53.899 91.001,59.8 92.701,59.8 94.401,59.8 90.732,65.899 92.432,65.899 94.132,65.899
PMBUS_SCL: J1.3 J4.3 | length 24.5
  Signal Layer 1 w0.2: v1(145.6,8) 146.51,8 151.5,12.99 151.5,16.6 152,17.1 153.5,17.1 J4.3@154.8,18.4
  Bottom Layer w0.2: J1.3@141.76,4.13 141.76,3.107 141.877,2.99 143.89,2.99 145.6,4.7 v1(145.6,8)
PMBUS_SDA: J1.1 J4.1 | length 23.7
  Signal Layer 1 w0.2: v1(144.276,7.976) 144.338,7.976 144.593,8.23 145.053,8.23 145.372,8.55 146.565,8.55 151.15,13.135 151.15,16.745 151.879,17.474 153.074,17.474 153.7,18.1 153.7,19.3 J4.1@154.8,20.4
  Bottom Layer w0.2: J1.1@143.03,4.13 143.06,4.1 143.9,4.1 144.601,4.801 144.601,7.651 v1(144.276,7.976)
PSON#: J1.15 J4.6 | length 30
  Top Layer w0.2: J1.15@134.14,4.13 134.97,3.3 144.5,3.3 153.4,12.2 153.4,14.4 154.45,15.45 156.45,15.45 156.7,15.7 156.7,16.2 J4.6@156.8,16.3
PWM-1H: Brd1.P1a pad.1@83.275,49.275 U13.15 | length 24.4
  Signal Layer 2 w0.2: pad.1@83.3,48.7 83.3,47.6 88.9,42 v1(92.4,42)
  Bottom Layer w0.2: v1(92.4,42) 93,42.6 U13.15@104.056,42.6
PWM-1H-s: J1.5 U13.2 | length 75.3
  Signal Layer 3 w0.2: v1(115.5,40.7) v1(117.4,42.6)
  Bottom Layer w0.2: U13.2@113.783,42.6 115.996,42.6 v1(117.4,42.6) ; v1(115.5,40.7) 116.7,40.7 118.3,39.1 118.3,35.2 119.7,33.8 126.1,33.8 126.95,32.95 126.95,25.045 129.15,22.845 129.15,12.75 133.2,8.7 145.9,8.7 146.5,8.1 146.5,4.595 144.305,2.4 141.3,2.4 140.49,3.21 J1.5@140.49,4.13
PWM-1L: Brd1.P6a pad.1@86.25,52.45 U13.14 | length 29.4
  Signal Layer 2 w0.2: pad.1@86.4,53 86.25,53.15 86.25,53.45 86.7,53.9 87.6,53.9 88.3,53.2 88.3,45.1 89.6,43.8 94.1,43.8 95.3,42.6 v1(95.3,41.3)
  Bottom Layer w0.2: v1(95.3,41.3) U13.14@104.261,41.3
PWM-1L-s: J1.7 U13.3 | length 74
  Bottom Layer w0.2: U13.3@113.366,41.2 113.615,41.45 116.65,41.45 118.8,39.3 118.8,35.4 120.05,34.15 126.245,34.15 127.3,33.095 127.3,25.19 129.5,22.99 129.5,12.895 133.345,9.05 146.045,9.05 146.85,8.245 146.85,4.45 144.3,1.9 140.8,1.9 139.22,3.48 J1.7@139.22,4.13
PWM-2H: Brd1.P1b pad.1@83.275,61.375 U13.13 | length 36.4
  Signal Layer 2 w0.2: pad.1@83.4,60.9 83.3,60.8 83.3,58.7 88.7,53.3 88.7,45.4 89.9,44.2 94.4,44.2 96.7,41.9 v1(96.7,40.1)
  Bottom Layer w0.2: v1(96.7,40.1) U13.13@104.083,40.1
PWM-2H-s: J1.4 U13.4 | length 54.9
  Bottom Layer w0.2: U13.4@113.783,40.027 116.173,40.027 117.9,38.3 117.9,35 119.5,33.4 126,33.4 126.6,32.8 126.6,24.9 128.8,22.7 128.8,12.49 134.24,7.05 139.83,7.05 141.346,5.534 141.626,5.534 J1.4@141.76,5.4
PWM-2L: Brd1.P6b pad.1@86.25,64.35 U13.12 | length 41.4
  Signal Layer 2 w0.2: pad.1@86.2,64.9 89.5,64.9 89.5,53.8 89.5,46.7 91.2,45 95.4,45 98,42.4 v1(98,38.8)
  Bottom Layer w0.2: v1@98,38.765 U13.12@104.025,38.765
PWM-2L-s: J1.6 U13.5 | length 52.8
  Bottom Layer w0.2: U13.5@113.432,38.9 115.9,38.9 117.446,37.354 117.446,34.754 119.2,33 125.5,33 126.25,32.25 126.25,24.755 128.45,22.555 128.45,12.345 134.095,6.7 138.91,6.7 140.076,5.534 140.356,5.534 J1.6@140.49,5.4
PWOK: J2.1 J4.13 | length 47.4
  Signal Layer 1 w0.2: J2.1@110.93,4.13 112.77,4.13 114.85,2.05 147.05,2.05 153.4,8.4 J4.13@154.8,8.4
RELAY_CTRL: C68.1 J22M.1 U11.1 | length 14.2
  Top Layer w0.3: J22M.1@82.2,4 82.3,4.1 83,4.1 83,9 C68.1@82.2,9.8
  Bottom Layer w0.3: J22M.1@82.3,4 82.6,4 83.1,4.5 83.1,9.795 U11.1@82.345,10.55
RMT_SNS: J2.12 J4.11 R19.2 | length 64.6
  Signal Layer 1 w0.2: J2.12@104.58,5.4 104.714,5.534 104.714,5.814 105.9,7 112.1,7 116,3.1 145.3,3.1 152.6,10.4 J4.11@154.8,10.4
  Bottom Layer w0.3: R19.2@151.5,17.7 151.5,14.7 153.6,12.6 153.6,11.1 154.109,10.591 154.609,10.591 J4.11@154.8,10.4
RTN/PS_KILL: J2.10 J4.9 R18.1 | length 62.6
  Signal Layer 1 w0.2: J2.10@105.85,5.4 107.1,6.65 111.55,6.65 115.45,2.75 145.845,2.75 152.653,9.558 v1(153.201,9.558)
  Signal Layer 2 w0.2: v1(153.201,9.558) 153.201,10.801 J4.9@154.8,12.4
  Bottom Layer w0.2: v1(152.427,16.173) v1@152.4,16.173 ; R18.1@152.8,17.7 152.8,17.3 152.4,16.9 v1@152.4,16.173 ; J4.9@154.9,12.4 154.4,12.4 152.4,14.4 v1@152.4,16.173
SGND: C14.1 C16.2 C20.2 C21.2 C30.1 C34.2 C35.2 C36.2 C981.2 C982.2 D3.2 J1.19 J2.7 J2.8 J2.9 J2.11 J22A.5 J22A.7 J22A.8 R2.2 R3.2 R4.2 R5.2 R18.2 R21.1 R23.2 R24.1 RJ01.2 U3.2 U13.8 U15.4 U20.2 | length 330.8
  Top Layer w0.2: J22A.7@125,29.9 J22A.7@125.1,30
  Top Layer w0.5: v1@115.635,35.492 119.965,35.492 120.173,35.7 v1(120.2,35.7)
  Top Layer w1: J22A.5@123.73,29.9 J22A.7@125,29.9 J22A.8@125,31.17
  Signal Layer 1 w0.2: 119.7,4.6 119.8,4.6
  Signal Layer 1 w1: J22A.5@123.9,29.9 J22A.7@125,29.9 125,28 130.1,22.9 154.2,22.9 158.25,26.95 158.25,44.679 v5@157.664,45.265 ; v5(152.7,45.4) v5(154.1,45.4) v5(156,45.4) v5(157.4,45.4) v5@157.473,45.4
  Signal Layer 2 w0.2: v8@155.9,51.7 v8(155.9,53.1) v1@157.8,53.1 ; v1(157.763,53.036) 158.364,53.036 158.5,52.9 158.5,25.4 v1(158.1,25)
  Signal Layer 2 w1: J22A.8@125,31.17 125,38.914 125.586,39.5 131.1,39.5 132.7,41.1 147,41.1 150.9,45 152.227,45 152.627,45.4 v5(152.7,45.4)
  Signal Layer 3 w0.5: v1(128.5,43.8) 128.5,43.773 128.1,43.373 128.1,36.593 126.7,35.193 126.7,8.5 130.993,4.207 131.523,4.207 J1.19@131.6,4.13
  Bottom Layer w0.2: C16.2@115.5,34.7 v1@115.5,35.4 ; J22A.8@125,31.17 J22A.8@125,31.2 ; RJ01.2@149.606,44.706 149.712,44.6 155.1,44.6 155.1,45 ; R18.2@152.8,18.9 152.8,21.3 156.5,25 v1(158.1,25)
  Bottom Layer w0.3: U13.8@113.775,34.955 113.925,35.105 114.505,35.105 114.8,35.4 v1@115.5,35.4 ; C982.2@119.1,8.099 119.3,8.299 v1(120.5,8.299) 121.2,8.299 121.3,8.399 U20.2@121.3,9.574 ; 121.3,8.276 123.55,8.276 123.7,8.126 C981.2@123.7,8.1 ; U15.4@124.25,19.34 124.25,19.525 124.34,19.525 124.516,19.701 124.516,21.616 C34.2@125.3,22.4 ; C30.1@124.6,20.6 125.941,20.6 126.11,20.431 126.124,20.431 126.5,20.055 126.5,17.376 126.324,17.2 125.6,17.2 125.3,16.9 R21.1@125.3,16.4 ; C35.2@125.183,11.117 C35.2@125.565,11.5 ; C14.1@136.65,37.2 136.65,38.75 C21.2@136.7,38.8 136.7,38.825 137.375,39.5 U3.2@138.35,39.5 138.5,39.65 139.724,39.65 139.9,39.826 139.9,41 140.5,41.6 142.175,41.6 142.325,41.75 142.325,42.075 142.675,42.425 C20.2@142.975,42.425
  Bottom Layer w0.4: v1(120.2,35.7) 121.3,34.6 126.431,34.6 127.75,33.281 127.75,25.376 129.95,23.176 129.95,13.25 133.7,9.5 146.231,9.5 147.3,8.431 147.3,3.6 145.1,1.4 133.2,1.4 131.696,2.904 131.696,4.034 J1.19@131.6,4.13 ; D3.2@133.408,41.81 D3.2@133.7,41.81
  Bottom Layer w0.5: C35.2@125.05,11.25 C35.2@125.1,11.2 125.3,11.4 R23.2@125.3,15.3 ; C36.2@125.116,13.3 C36.2@125.166,13.25 ; R23.2@125.277,15.29 R21.1@125.277,16.474 ; R24.1@128.4,44.4 128.431,44.4 128.481,44.35 128.481,43.819 v1(128.5,43.8)
  Bottom Layer w0.8: J22A.5@123.73,29.9 J22A.7@125,29.9 J22A.8@125,31.17
  Bottom Layer w1: D3.2@132.828,42.389 D3.2@133.408,41.81 ; D3.2@133.7,41.81 134.279,42.389 135.047,42.389 135.157,42.5 C20.2@142.9,42.5 ; C20.2@142.975,42.425 143.568,42.425 143.586,42.407 144.414,42.407 145,42.993 145,44.4 146.571,45.971 151.329,45.971
  other v1: 125.3,15.9 124.454,21.131 115.608,35.492 155.9,51.2 156.763,51.436 154.9,51.5 157.463,52.036 154.3,52.2 154,53.1 157.5,54 154.3,54.1 155,54.7 156.9,54.7 155.9,55
SGND-1: Brd1.S7 C4.2 C4A.2 C5.2 C6.2 R2.1 R3.1 R4.1 R5.1 RJ02.2 | length 6.7
  Bottom Layer w0.2: RJ02.2@149.712,43.3 149.712,43.888 150.074,44.25 155.1,44.25 v5@155.1,43.643
  other v1: 144.736,48.86 145.768,48.86 146.8,48.86 144.736,54.84 145.768,54.84 146.8,54.84 144.726,58.83 145.758,58.83 146.79,58.83 144.74,60.83 145.77,60.82 146.8,60.82 144.736,64.88 145.768,64.88 146.8,64.88
  other v4: 144.764,52.82 145.796,52.82 146.828,52.82
  other v5: 152.2,43.4 153.6,43.4 155.5,43.4 156.9,43.4
SMB_ALERT#: J1.17 J4.7 | length 28.3
  Top Layer w0.2: J1.17@132.87,4.13 134.2,2.8 144.566,2.8 153.8,12.034 153.8,13.7 154.5,14.4 J4.7@154.8,14.4
SR-1H: Brd1.S2 J1.9 pad.1@151.15,52.25 pad.1@151.15,58.35 pad.1@151.15,64.35 | length 145.6
  Top Layer w0.2: v1(133.7,53.4) 134.339,54.039 150.261,54.039 151.15,53.15 pad.1@151.15,52.25 ; v1(133.7,59.5) 134.3,60.1 150.1,60.1 151.15,59.05 pad.1@151.15,58.35
  Signal Layer 2 w0.2: v1@133.564,65.364 134.6,66.4 150.2,66.4 151.114,65.486 ; v1@133.612,59.412 v1@133.629,59.412 ; v1@133.676,53.376 v1(133.7,53.4) ; pad.1@151.15,64.35 151.15,65.45
  Signal Layer 3 w0.2: v1(133.7,53.4) 133.7,53.417 134,53.717 134,59.183 133.7,59.483 v1(133.7,59.5) 133.7,61.3 ; v1@133.7,65.67 133.7,61.4 133.7,61.3 ; J1.9@137.95,4.13 137.95,2.95 137.2,2.2 129.827,2.2 127.821,4.206 125.85,6.177 125.85,35.545 126.6,36.295 126.6,36.3 127.25,36.95 127.25,58.323 130.327,61.4 133.6,61.4 133.7,61.3
  other v1: 133.7,65.5
SR-1L: Brd1.S1 J1.11 pad.1@151.075,49.275 pad.1@151.075,55.375 pad.1@151.075,61.375 | length 145.3
  Signal Layer 2 w0.2: v1(132.6,47.6) 143.004,47.6 143.454,47.15 150.35,47.15 151.1,47.9 pad.1@151.1,49 ; v1(132.6,53.7) 132.667,53.7 132.917,53.95 134.528,53.95 134.978,53.5 150.15,53.5 151.1,54.45 151.1,54.8 ; v1(132.6,59.8) 132.708,59.8 133.058,60.15 139.55,60.15 140.2,59.5 150.3,59.5 151.2,60.4 151.2,61
  Signal Layer 3 w0.2: v1(132.6,47.6) v1(132.6,53.7) 133.35,54.45 133.35,59.05 v1(132.6,59.8) 132.6,60.6 132.15,61.05 130.472,61.05 127.6,58.178 127.6,36.8 126.2,35.4 126.2,6.322 128.171,4.351 129.972,2.55 136.05,2.55 136.68,3.18 J1.11@136.68,4.13
SR-2H: Brd1.S4 J1.8 pad.1@149.65,52.25 pad.1@149.65,58.35 pad.1@149.65,64.35 | length 120.7
  Top Layer w0.2: v1(134.6,53.1) 135.189,53.689 149.111,53.689 149.65,53.15 pad.1@149.65,52.25 ; v1(134.6,59.2) 135.15,59.75 148.95,59.75 149.65,59.05 pad.1@149.65,58.35
  Signal Layer 2 w0.2: v1@134.52,53.02 134.618,53.02 v1@134.649,53.051 ; v1(134.6,59.2) v1@134.708,59.2 ; v1(134.6,65.2) 135.45,66.05 148.75,66.05 149.65,65.15 pad.1@149.65,64.35
  Signal Layer 3 w0.2: v1@134.6,65.254 v1(134.6,53.1) 134.6,48.3 133.85,47.55 133.672,47.55 133.35,47.228 133.35,47.05 128.95,42.65 128.95,34.677 127.9,33.627 127.9,10.795 131.795,6.9 138.3,6.9 139.18,6.02 139.18,5.44 J1.8@139.22,5.4
SR-2L: Brd1.S3 J1.10 pad.1@149.575,49.275 pad.1@149.575,55.375 pad.1@149.575,61.375 | length 123.3
  Signal Layer 2 w0.2: v1(131.6,48) 131.708,48 131.858,48.15 132.828,48.15 133.028,47.95 143.149,47.95 143.599,47.5 148.9,47.5 149.6,48.2 pad.1@149.6,49 ; v1(131.6,54.1) 131.708,54.1 131.908,54.3 134.673,54.3 135.073,53.9 149.1,53.9 149.6,54.4 pad.1@149.6,55.1 ; v1(131.6,60.2) 131.631,60.231 132.018,60.231 132.287,60.5 139.695,60.5 140.345,59.85 148.95,59.85 149.6,60.5 149.6,61 ; pad.1@149.575,61.121 pad.1@149.575,61.375
  Signal Layer 3 w0.2: v1(131.6,60.2) 131.624,60.176 131.624,59.776 132.7,58.7 132.7,54.9 131.974,54.174 131.674,54.174 v1(131.6,54.1) v1(131.6,48) 131.526,47.926 131.526,45.721 128.6,42.795 128.6,34.822 127.55,33.772 127.55,10.45 131.7,6.3 137.545,6.3 137.867,5.978 137.867,5.483 J1.10@137.95,5.4
SWNODE: L4.2 pad.1@37.998,61.696 pad.1@39.875,60.95 pad.1@39.975,61.7 pad.1@40.025,62.425 pad.1@41.948,61.696 | length 0.7
  Signal Layer 3 w2: pad.1@39.7,62 pad.1@40.2,61.5
TEMP_3: J21M.5 pad.1@71.175,60.575 | length 66.4
  Signal Layer 2 w0.3: J21M.5@63,4.1 63,3.7 63.6,3.1 66,3.1 66.5,3.6 66.5,15.6 70.5,19.6 70.5,33.4 74.9,37.8 74.9,55.5 71.175,59.225 v2(71.175,60.1) pad.1@71.175,60.575
TEMP_OUT: J21M.11
TMP_PRI: J21M.3
VBB: Brd1.P8a Brd1.P8b C2.2 C3.1 D11.2 J21A.1 J21A.2 Q5.9 R50.2 | length 7.3
  Signal Layer 2 w0.3: J21A.2@91.87,31.17 J21A.2@91.9,31.2
  Bottom Layer w1: v3@66.677,36.9 71.65,36.9 72.45,36.1 R50.2@73.6,36.1
  other v3: 61.5,36.1 62.8,36.1 64.1,36.1 65.4,36.1 66.7,36.1 61.5,37.4 62.8,37.4 64.1,37.4 65.4,37.4 66.7,37.4 99.017,47.8 100.717,47.8 102.417,47.8 72.7,49.5 72.7,50.8 72.7,52.1 72.7,53.4 98.748,53.899 100.448,53.899 102.148,53.899 99.018,59.8 100.718,59.8 102.418,59.8 98.749,65.899 100.449,65.899 102.149,65.899
VBB_FB: J22M.12 R52.1 | length 22.6
  Bottom Layer w0.2: R52.1@73.6,23.55 72.05,23.55 70.5,22 70.5,12.6 72,11.1 72,9.6 75.88,5.72 J22M.12@75.88,5.4
Vbulk: C39.2 C40.1 C67.1 C74.2 C114.2 C120.2 C123.2 C130.2 L1.2 Q4.2 Q4.3-4-5-6-7-8 Q5.2 Q5.3-4-5-6-7-8 R47.2 R57.1 R65.2 RT2.2 U11.9 U11.14 | length 61.5
  Top Layer w0.3: C120.2@43.1,18.25 43.1,18.58 44.32,19.8 56.2,19.8 R47.2@56.4,19.6
  Signal Layer 1 w1: RT2.2@31.1,24.7 31.1,18.5 42.85,18.5 C120.2@43.1,18.25
  Bottom Layer w0.2: C39.2@56.2,41.8 R57.1@57.8,41.8 57.8,41.3 58.5,40.6 60,40.6 60.6,41.2 Q5.2@60.6,42.15 ; Q4.2@66.8,46.05 67.1,46.35 67.1,47.8 69.1,47.8 69.8,47.1 70.4,47.1 C40.1@72,47.1 ; U11.9@73.455,16.05 U11.9@73.5,16.005 ; C67.1@73.5,18.8 C67.1@73.6,18.9 ; C74.2@79.2,19.2 C74.2@79.5,18.9
  Bottom Layer w0.3: C39.2@56.2,41.6 C39.2@56.3,41.5
  Bottom Layer w0.4: C74.2@79.2,19.2 v2(79.2,20.5)
  Bottom Layer w0.5: C67.1@73.6,18.9 73.455,18.755 U11.9@73.455,16.05 73.455,15.045 73.9,14.6 79.1,14.6 79.8,15.3 U11.14@79.8,16.2 ; U11.14@79.805,16.2 C74.2@79.805,17.995
  other v3: 61.5,43.8 62.8,43.8 64.1,43.8 65.4,43.8 66.7,43.8
Vbulk1: C52.1 C53.1 D1.4 pad.1@59.825,61.725 pad.1@61.775,60.975 pad.1@61.775,62.475 pad.1@61.825,61.725 pad.1@63.825,61.725 Q4.9 RT2.1 | length 56.6
  Top Layer w1: C52.1@55.3,67.75 C52.1@55.35,67.7
  Signal Layer 2 w2: RT2.1@36.1,24.7 36.1,49.2 40.7,53.8 59.1,53.8 62.8,57.5 v3(62.8,59)
  Bottom Layer w1: pad.1@62.1,61.6 pad.1@62.4,61.9
  other v3: 61.4,59 64.2,59 65.6,59
Vbulk_SNS: J22M.20 R49.1 | length 20.1
  Top Layer w0.2: v2(67.9,19.8) 68.1,19.6 R49.1@69.15,19.6
  Bottom Layer w0.2: v2(67.9,19.8) 69.5,19.8 69.9,19.4 69.9,12.7 68.5,11.3 68.5,6.1 69.1,5.5 70.8,5.5 J22M.20@70.9,5.4
VCR_sns: C1.2 J2.17 R10.1 | length 76.5
  Signal Layer 3 w0.2: J2.17@100.77,4.13 100.77,3.67 100.5,3.4 98.45,3.4 97.65,4.2 97.65,6.505 98.595,7.45 102.65,7.45 105.6,10.4 105.6,10.405 105.65,10.455 105.65,16.55 112.7,23.6 112.7,36.3 121.25,44.85 121.25,45.528 124.1,48.378 124.1,57.984 124.9,58.784 v1(124.9,60.1)
  Bottom Layer w0.2: v1(124.9,60.1) 125.6,59.4 125.6,59.2 125.8,59 R10.1@125.9,59
  Bottom Layer w0.3: R10.1@126,58.9 126.3,58.6 C1.2@126.3,57.7
VI_LOCAL: C7.2 R1.1 R7.1 R15.1 U2.1 | length 44.9
  Signal Layer 3 w0.2: v1(108.1,9.1) 108.1,9.725 114,15.625 114,20.657 114.171,20.828 v1(114.171,21.308) ; v1@114.171,21.377 114.359,21.377 115.8,22.817 115.8,34 119.625,37.825 v1(121.207,37.825)
  Bottom Layer w0.2: R7.1@106.8,9.5 107.651,9.5 108.051,9.1 v1(108.1,9.1) ; v1(114.171,21.308) R15.1@115.871,21.308
  Bottom Layer w0.3: U2.1@121.25,42.875 121.287,42.838 121.287,41.925 122,41.212 122,39.375 121.225,38.6 C7.2@121.2,38.6 121.2,37.6 121.6,37.2 R1.1@121.7,37.2
VINOK: J1.2 J4.14 | length 15.4
  Signal Layer 2 w0.2: J1.2@143.03,5.4 151.4,5.4 152.9,6.9 155.9,6.9 156.8,7.8 J4.14@156.8,8.4
ZCD: C52.2 C53.2 C64.2 C65.2 C66.2 D2.1 D2.3 pad.1@30.85,60.55 pad.1@46.925,61.7 pad.1@48.9,60.95 pad.1@48.9,62.425 pad.1@48.85,61.7 pad.1@50.775,61.7 R43.1 R150.2 U9.4 | length 42.6
  Top Layer w0.2: pad.1@48.85,61.7 pad.1@48.85,62.45
  Signal Layer 1 w0.5: 33.6,31.3 33.6,63 38.875,68.275 v2(39.35,68.275)
  Signal Layer 4 w0.2: pad.1@48.8,61.75 pad.1@48.85,61.7
  Bottom Layer w0.2: R43.1@36.3,16.5 36.3,16.8 36.6,16.8 36.897,17.097 36.883,17.111 36.883,17.183 v2(36.9,17.2)
  Bottom Layer w0.6: C66.2@34.6,64.525 34.625,64.55 C66.2@34.625,64.725 ; 38.325,67.475 C65.2@38.325,68.225
  other v2: 30.85,60.05
  other v3: 34.7,20.4 36,20.4 37.3,20.4 38.6,20.4
ZCD_Amp: J21M.2 R42.2 U4.1 | length 40.5
  Signal Layer 3 w0.3: v2@33,15.3 35.2,13.1 55.6,13.1 62.1,6.6 64.7,6.6 65.6,5.7 J21M.2@65.6,5.4
  Bottom Layer w0.3: v2@33,15.3 R42.2@35.1,15.3 35.1,14.1 U4.1@35.3,13.9
  other v2: 32.9,15.3
pads on no net: J21A.3 J21A.4 J21A.5 J21A.6 J21A.9 J21A.10 J21A.11 J21A.12 J21A.15 J21A.16 J21A.17 J21A.18 J21M.12 J21M.14 J21M.16 J21M.17 J22A.1 J22M.4 J22M.7 J22M.10 J22M.15 U6.8 U6.9 U6.11@112.325,17.775 U10.4 U11.6 U11.7 U11.12 U11.13 U13.6 U15.6 U20.4 U31.5

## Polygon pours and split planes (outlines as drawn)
5Vp on Top Layer "TOP_LAYER_NONET_P535" (solid, remove dead copper, pour order 530): 29 vertices, not listed, extent 56.7,7.4 87.2,14.4
54Vout-1 on Top Layer "TOP_LAYER_54VOUT-1_P403" (solid, remove dead copper, pour order 403): 17 vertices, not listed, extent 126.7,7.1 157.7,42.7
12VS on Top Layer "Top Layer-12VS" (solid, remove dead copper, pour order 575): 112.082,24.582 107.8,20.3 107.8,4.4 126.3,4.4 126.3,25.3 126.3,47.99 121.357,47.99 112.082,38.587
ZCD on Top Layer "TOP_LAYER_ZCD_P568" (solid, remove dead copper, pour order 568): 46.9,60.4 47.3,60 51.7,60 52,60.3 52,63.7 50.1,65.6 35.7,65.6 33.4,63.3 33.4,59.4 34,58.8 34.8,58.8 34.8,63.9 36.1,65.2 46.5,65.2 46.9,64.8
SGND-1 on Top Layer "Top Layer-SGND-1" (solid, remove dead copper, pour order 555): 144.3,40.7 158.5,40.7 158.5,44.1 158.3,44.3 151.9,44.3 151.2,45 151.2,47.7 148.4,47.7 147.4,48.7 147.4,69.1 144.3,69.1
PGND on Top Layer "TOP_LAYER_PGND_P404" (solid, remove dead copper, pour order 404): 76.1,56.2 76.867,56.967 87.267,56.967 89.724,59.424 89.724,61.625 95.1,61.5 95.1,45.9 88,38.8 76.8,38.8 76.1,39.5
MID-1 on Top Layer "TOP_LAYER_MID-1_P553" (solid, remove dead copper, pour order 553): 105.379,55.3 110.879,55.3 111.479,54.7 111.479,46.7 105.379,46.7
MID-2 on Top Layer "TOP_LAYER_MID-2_P550" (solid, remove dead copper, pour order 550): 105.38,67.3 110.88,67.3 111.48,66.7 111.48,58.7 105.38,58.7
VBB on Top Layer "TOP_LAYER_VBB_P549" (solid, remove dead copper, pour order 549): 97.65,67.3 103.15,67.3 103.75,66.7 103.75,46.4 97.65,46.4
PGND on Top Layer "TOP_LAYER_PGND_P548" (solid, remove dead copper, pour order 548): 89.664,67.151 95.164,67.151 95.164,46.251 89.664,46.251
PGND on Top Layer "TOP_LAYER_PGND_P543" (solid, remove dead copper, pour order 543): 85.7,20.3 94.7,29.3 94.7,31.6 103.7,31.6 104.7,30.6 104.7,27 94.2,16.5 86.5,16.5 85.7,17.3
SGND on Top Layer "TOP_LAYER_SGND_P503" (solid, remove dead copper, pour order 503): 151.4,62.1 158.534,62.1 158.534,45.53 157.703,44.7 151.4,44.7
PGND on Top Layer "TOP_LAYER_PGND_P535" (solid, remove dead copper, pour order 535): 50,1.6 50.6,1 87.6,1 87.6,2.5 89.1,4 89,4.1 89,11.3 50,11.3
N on Top Layer "TOP_LAYER_N_P442" (solid, remove dead copper, pour order 442): 37.3,4.3 38.6,5.6 46.7,5.6 46.9,5.4 46.9,1.4 46.3,0.8 37.9,0.8 37.3,1.4
NetR48_1 on Top Layer "TOP_LAYER_NETR48_1_P537" (solid, remove dead copper, pour order 537): 63.611,20.468 67.011,20.468 67.011,18.668 63.611,18.668
NetR47_1 on Top Layer "TOP_LAYER_NETR47_1_P536" (solid, remove dead copper, pour order 536): 58.7,20.5 62.1,20.5 62.1,18.7 58.7,18.7
PE on Top Layer "TOP_LAYER_PE_P519" (solid, remove dead copper, pour order 519): 7.6,62.9 9,61.5 10.8,61.5 16.2,66.9 16.2,69.4 16,69.6 8.2,69.6 7.6,69
PE on Top Layer "TOP_LAYER_PE_P518" (solid, remove dead copper, pour order 518): 7.2,0.5 8.2,1.5 8.2,12.4 6.7,13.9 1.5,13.9 0.5,12.9 0.5,2.3 2.3,0.5 0.7,2.1 2.3,0.5
54Vout on Top Layer "TOP_LAYER_54VOUT_P539" (solid, remove dead copper, pour order 539): 144.15,35.3 158,35.3 158.5,35.8 158.5,40.4 143.65,40.4 143.65,35.8
Vbulk1 on Top Layer "TOP_LAYER_VBULK1_P501" (solid, remove dead copper, pour order 501): 34.5,24 36.5,24 37.2,24.7 37.2,31.7 39.3,33.8 41.8,33.8 42.1,34.1 42.1,40.6 35.6,40.6 35.3,40.3 35.3,33.5 33.4,31.6 33.4,25.1
VBB on Top Layer "TOP_LAYER_VBB_P497" (solid, remove dead copper, pour order 497): 82,35.7 88.8,28.9 92.1,28.9 92.4,29.2 92.4,33.9 89.4,36.9 75.4,36.9 72.9,39.4 69.2,35.7
NetD11_1 on Top Layer "TOP_LAYER_NETD11_1_P412" (solid, remove dead copper, pour order 412): 57.3,30.4 76.1,30.4 79.4,33.7 80.9,33.7 81.1,33.5 81.1,30 76.8,25.7 70.8,25.7 68.8,23.7 54.5,23.7 53.2,25 53.2,26.3
NetBrd1_S8 on Top Layer "TOP_LAYER_NETBRD1_S8_P473" (solid, remove dead copper, pour order 473): 144.1,69.2 144.1,43.1 127.35,43.1 126.1,44.35 126.1,65 130.3,69.2
Line on Top Layer "TOP_LAYER_LINE_P467" (solid, remove dead copper, pour order 467): 23 vertices, not listed, extent 25.6,29.6 55.1,57.9
Neutral on Top Layer "TOP_LAYER_NEUTRAL_P454" (solid, remove dead copper, pour order 454): 8.1,48.5 17.5,48.5 22.6,53.6 22.6,65.2 21.8,66 19.7,66 8.1,54.4
NetC44_1 on Top Layer "TOP_LAYER_NETC44_1_P452" (solid, remove dead copper, pour order 452): 24.488,49.6 25.625,49.6 29.3,45.68 29.3,28.6 26.6,25.9 26.6,13.2 25.9,12.5 23.4,12.5 22.9,13 22.9,47.029
NetC41_2 on Top Layer "TOP_LAYER_NETC41_2_P451" (solid, remove dead copper, pour order 451): 8.1,17.8 12.1,13.8 19.1,13.8 19.9,14.6 19.9,46.2 8.1,46.2
ZCD on Top Layer "TOP_LAYER_ZCD_P443" (solid, remove dead copper, pour order 443): 32.9,16.9 39,16.9 39.9,17.8 39.9,21.2 38.9,22.2 33.2,22.2 31.8,20.8 31.8,18
Nout on Top Layer "TOP_LAYER_NOUT_P435" (solid, remove dead copper, pour order 435): 43,8 46.7,8 47,7.7 47,6.2 46.6,5.8 42.8,5.8 42.5,6.1 42.5,7.5
Lout on Top Layer "TOP_LAYER_LOUT_P430" (solid, remove dead copper, pour order 430): 11.7,7.7 13.3,9.3 15.7,9.3 20.7,4.3 30.8,4.3 30.8,1.4 30.1,0.7 12.9,0.7 11.7,1.9
Vbulk1 on Top Layer "TOP_LAYER_VBULK1_P422" (solid, remove dead copper, pour order 422): 52.7,68.9 53.2,69.4 66,69.4 66.9,68.5 66.9,58.5 65.9,57.5 59,57.5 58.1,58.4 58.1,66.4 57.4,67.1 53.2,67.1 52.7,67.6
ZCD on Top Layer "TOP_LAYER_ZCD_P423" (solid, remove dead copper, pour order 423): 18 vertices, not listed, extent 35.2,55 56.9,65.6
PGND on Top Layer "TOP_LAYER_PGND_P417" (solid, remove dead copper, pour order 417): 32.9,13.1 34.2,14.4 45.9,14.4 47.4,12.9 47.4,11 46.4,10 41.5,10 40.2,8.7 32.8,8.7 32.9,8.8
VBB on Top Layer "TOP_LAYER_VBB_P414" (solid, remove dead copper, pour order 414): 64.1,56.7 72.1,56.7 73.2,55.6 73.2,39.1 67.8,33.7 58.2,33.7 56.2,35.7 56.2,48.8
PGND on Top Layer "TOP_LAYER_PGND_P400" (solid, remove dead copper, pour order 400): 78.7,59.25 73.95,59.25 73.924,59.274 73.391,59.807 73.391,60.682 73.541,60.832 75.166,60.832 75.766,61.432 75.766,63.482 76.216,63.932 78.675,63.932 79,63.607 79,59.55
SGND-1 on Signal Layer 1 "SIGNAL_LAYER_1_SGND-1_P406" (solid, remove dead copper, pour order 406): 158.5,34.222 158.5,44.792 158.5,69.2 130,69.2 126.075,65.275 126.075,23 158.5,23
SGND on Signal Layer 1 "Signal Layer 1-SGND" (solid, remove dead copper, pour order 571): 18 vertices, not listed, extent 92.4,0.8 158.5,63.2
ZCD on Signal Layer 1 "SIGNAL_LAYER_1_ZCD_P567" (solid, remove dead copper, pour order 567): 48.3,60.1 48.7,59.7 53.1,59.7 53.4,60 53.4,63.4 51.5,65.3 37.1,65.3 34.8,63 34.8,59.1 35.4,58.5 36.2,58.5 36.2,63.6 37.5,64.9 47.9,64.9 48.3,64.5
VBB on Signal Layer 1 "SIGNAL_LAYER_1_VBB_P551" (solid, remove dead copper, pour order 551): 98,67.3 103.15,67.3 103.75,66.7 103.75,47.1 98,47.1
PE on Signal Layer 1 "SIGNAL_LAYER_1_PE_P531" (solid, remove dead copper, pour order 531): 7.6,62.9 9,61.5 10.8,61.5 16.2,66.9 16.2,69.4 16,69.6 8.2,69.6 7.6,69
PE on Signal Layer 1 "SIGNAL_LAYER_1_PE_P520" (solid, remove dead copper, pour order 520): 7.2,0.5 8.2,1.5 8.2,12.4 6.7,13.9 1.5,13.9 0.6,13 0.6,2.1 0.7,2.1 2.3,0.5 0.7,2.1 2.3,0.5
ZCD on Signal Layer 1 "SIGNAL_LAYER_1_ZCD_P505" (solid, remove dead copper, pour order 505): 20 vertices, not listed, extent 33.1,19.6 55.2,69.3
PGND on Signal Layer 1 "SIGNAL_LAYER_1_PGND_P436" (solid, remove dead copper, pour order 436): 17 vertices, not listed, extent 32.2,0.8 101.2,16
PGND on Signal Layer 1 "SIGNAL_LAYER_3_NONET_P484" (solid, remove dead copper, pour order 490): 96.9,69.4 96.9,46.9 104.7,39.1 104.7,23.5 103,21.8 103,12.9 99.2,9.1 55.4,9.1 52.1,12.4 52.1,42.3 79.2,69.4
Neutral on Signal Layer 1 "SIGNAL_LAYER_1_NEUTRAL_P483" (solid, remove dead copper, pour order 483): 8.1,49.9 18.9,49.9 24.5,55.5 24.5,65.1 23.6,66 18,66 8.1,56.1
NetC41_2 on Signal Layer 1 "SIGNAL_LAYER_1_NETC41_2_P469" (solid, remove dead copper, pour order 469): 8.1,17.8 12.1,13.8 19.1,13.8 19.9,14.6 19.9,47 8.1,47
NetC44_1 on Signal Layer 1 "SIGNAL_LAYER_1_NETC44_1_P464" (solid, remove dead copper, pour order 464): 24.088,46.9 28.156,46.9 29.7,45.253 29.7,26.3 28.9,25.5 28.9,13.4 27.8,12.3 22.3,12.3 21.3,13.3 21.3,42.386
N on Signal Layer 1 "SIGNAL_LAYER_1_N_P453" (solid, remove dead copper, pour order 453): 37.3,4.3 38.3,5.3 45.9,5.3 46.7,4.5 46.7,1.2 46.3,0.8 37.9,0.8 37.3,1.4
Nout on Signal Layer 1 "SIGNAL_LAYER_1_NOUT_P449" (solid, remove dead copper, pour order 449): 23.2,11.4 28.5,11.4 31.9,8 46.4,8 47.1,7.3 47.1,6.2 46.4,5.5 25.3,5.5 22.5,8.3 22.5,10.7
